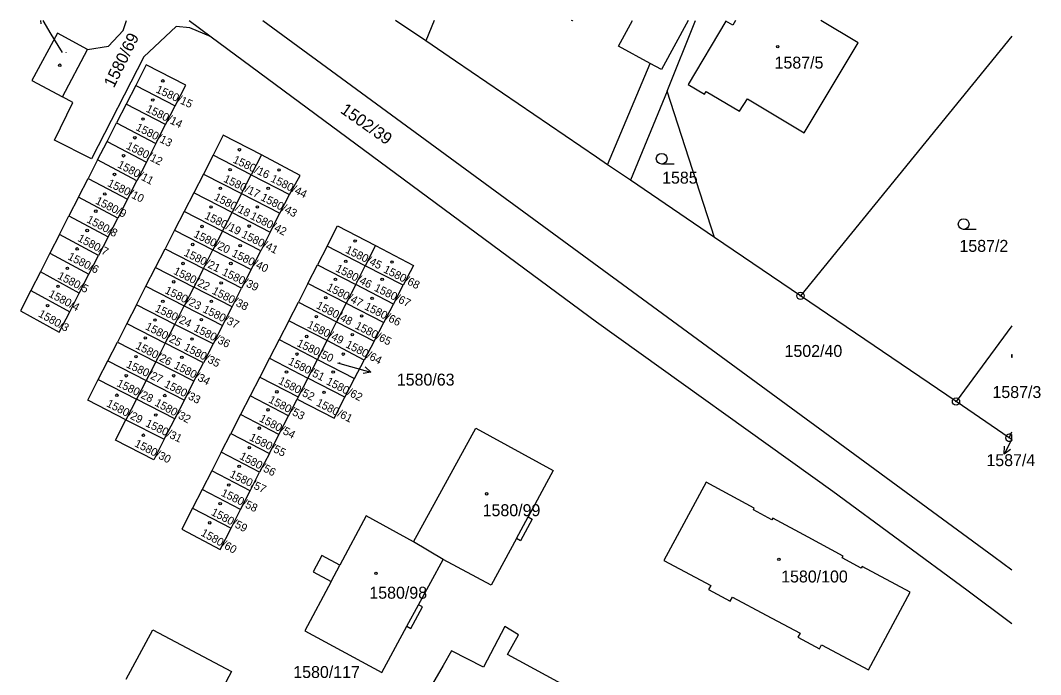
# Model space of a CAD drawing. Extents: x -736397 to -735924, y -1118983 to -1118245.
# Drawn here: x -736069.2 to -735924, y -1118338 to -1118244.9 of the extents above; entities that cross this region are included whole.
import ezdxf

# ---------------------------------------------------------------- set-up
doc = ezdxf.new("R2010")
doc.units = 0
for name, color, linetype in [('Vrstva 1', 7, 'Continuous'), ('Vrstva 16', 7, 'Continuous'), ('Vrstva 18', 7, 'Continuous'), ('Vrstva 19', 7, 'Continuous'), ('Vrstva 25', 7, 'Continuous'), ('Vrstva 4', 7, 'Continuous')]:
    doc.layers.add(name, color=color, linetype=linetype)

msp = doc.modelspace()

# ---------------------------------------------------------------- linework, layer by layer
at = {"layer": 'Vrstva 1'}
for p, q in [((-736045.18, -1118244.9), (-736042.03, -1118247.22)), ((-736011.5, -1118247.82), (-736015.8, -1118244.9)), ((-736010.3, -1118244.9), (-736011.5, -1118247.82)), ((-735928.04, -1118247.13), (-735958.15, -1118284.08)), ((-736063.22, -1118255.78), (-736059.67, -1118249.01)), ((-735985.62, -1118265.43), (-735979.55, -1118251.02)), ((-736052.8, -1118254.16), (-736054.14, -1118256.79)), ((-736052.8, -1118254.16), (-736047.17, -1118257.06)), ((-735977.15, -1118254.97), (-735982.36, -1118267.64)), ((-735970.38, -1118275.78), (-735977.15, -1118254.97)), ((-736054.14, -1118256.79), (-736055.53, -1118259.48)), ((-736048.53, -1118259.7), (-736054.14, -1118256.79)), ((-736048.53, -1118259.7), (-736047.17, -1118257.06)), ((-736056.88, -1118262.13), (-736055.53, -1118259.48)), ((-736055.53, -1118259.48), (-736049.91, -1118262.41)), ((-736049.91, -1118262.41), (-736048.53, -1118259.7)), ((-736058.23, -1118264.75), (-736056.88, -1118262.13)), ((-736056.88, -1118262.13), (-736051.28, -1118265.07)), ((-736049.91, -1118262.41), (-736051.28, -1118265.07)), ((-736058.23, -1118264.75), (-736059.57, -1118267.39)), ((-736052.63, -1118267.71), (-736058.23, -1118264.75)), ((-736041.79, -1118264.08), (-736043.16, -1118266.75)), ((-736036.34, -1118266.87), (-736041.79, -1118264.08)), ((-736034.89, -1118264.03), (-736036.34, -1118266.87)), ((-736051.28, -1118265.07), (-736052.63, -1118267.71)), ((-735982.36, -1118267.64), (-735985.62, -1118265.43)), ((-736060.94, -1118270.06), (-736059.57, -1118267.39)), ((-736059.57, -1118267.39), (-736053.98, -1118270.35)), ((-736053.98, -1118270.35), (-736052.63, -1118267.71)), ((-736043.16, -1118266.75), (-736044.52, -1118269.42)), ((-736043.16, -1118266.75), (-736037.71, -1118269.54)), ((-736037.71, -1118269.54), (-736036.34, -1118266.87)), ((-736036.34, -1118266.87), (-736030.89, -1118269.66)), ((-735970.38, -1118275.78), (-735982.36, -1118267.64)), ((-736060.94, -1118270.06), (-736062.3, -1118272.71)), ((-736055.36, -1118273.04), (-736060.94, -1118270.06)), ((-736053.98, -1118270.35), (-736055.36, -1118273.04)), ((-736044.52, -1118269.42), (-736045.89, -1118272.08)), ((-736039.08, -1118272.21), (-736044.52, -1118269.42)), ((-736037.71, -1118269.54), (-736039.08, -1118272.21)), ((-736037.71, -1118269.54), (-736032.26, -1118272.33)), ((-736032.26, -1118272.33), (-736030.89, -1118269.66)), ((-736045.89, -1118272.08), (-736047.25, -1118274.74)), ((-736040.44, -1118274.87), (-736045.89, -1118272.08)), ((-736040.44, -1118274.87), (-736039.08, -1118272.21)), ((-736039.08, -1118272.21), (-736033.63, -1118275)), ((-736063.65, -1118275.35), (-736062.3, -1118272.71)), ((-736062.3, -1118272.71), (-736056.73, -1118275.7)), ((-736056.73, -1118275.7), (-736055.36, -1118273.04)), ((-736033.63, -1118275), (-736032.26, -1118272.33)), ((-736047.25, -1118274.74), (-736048.61, -1118277.4)), ((-736047.25, -1118274.74), (-736041.8, -1118277.52)), ((-736040.44, -1118274.87), (-736041.8, -1118277.52)), ((-736034.99, -1118277.66), (-736040.44, -1118274.87)), ((-736033.63, -1118275), (-736034.99, -1118277.66)), ((-736063.65, -1118275.35), (-736065.01, -1118278)), ((-736058.09, -1118278.36), (-736063.65, -1118275.35)), ((-736056.73, -1118275.7), (-736058.09, -1118278.36)), ((-735958.15, -1118284.08), (-735970.38, -1118275.78)), ((-736065.01, -1118278), (-736066.37, -1118280.67)), ((-736065.01, -1118278), (-736059.45, -1118281.02)), ((-736049.97, -1118280.06), (-736048.61, -1118277.4)), ((-736048.61, -1118277.4), (-736043.16, -1118280.19)), ((-736043.16, -1118280.19), (-736041.8, -1118277.52)), ((-736041.8, -1118277.52), (-736036.35, -1118280.31)), ((-736036.35, -1118280.31), (-736034.99, -1118277.66)), ((-736025.55, -1118277), (-736026.91, -1118279.65)), ((-736020.11, -1118279.8), (-736025.55, -1118277)), ((-736018.64, -1118276.93), (-736020.11, -1118279.8)), ((-736059.45, -1118281.02), (-736058.09, -1118278.36)), ((-736066.37, -1118280.67), (-736067.73, -1118283.31)), ((-736060.83, -1118283.7), (-736066.37, -1118280.67)), ((-736051.33, -1118282.71), (-736049.97, -1118280.06)), ((-736049.97, -1118280.06), (-736044.53, -1118282.85)), ((-736043.16, -1118280.19), (-736044.53, -1118282.85)), ((-736037.71, -1118282.97), (-736043.16, -1118280.19)), ((-736036.35, -1118280.31), (-736037.71, -1118282.97)), ((-736028.27, -1118282.31), (-736026.91, -1118279.65)), ((-736026.91, -1118279.65), (-736021.46, -1118282.45)), ((-736021.46, -1118282.45), (-736020.11, -1118279.8)), ((-736014.71, -1118282.58), (-736020.11, -1118279.8)), ((-736060.83, -1118283.7), (-736059.45, -1118281.02)), ((-736028.27, -1118282.31), (-736029.64, -1118284.98)), ((-736022.83, -1118285.11), (-736028.27, -1118282.31)), ((-736067.73, -1118283.31), (-736062.19, -1118286.35)), ((-736062.19, -1118286.35), (-736060.83, -1118283.7)), ((-736052.68, -1118285.35), (-736051.33, -1118282.71)), ((-736051.33, -1118282.71), (-736045.88, -1118285.5)), ((-736044.53, -1118282.85), (-736045.88, -1118285.5)), ((-736039.08, -1118285.64), (-736044.53, -1118282.85)), ((-736039.08, -1118285.64), (-736037.71, -1118282.97)), ((-736021.46, -1118282.45), (-736022.83, -1118285.11)), ((-736016.09, -1118285.25), (-736021.46, -1118282.45)), ((-736016.09, -1118285.25), (-736014.71, -1118282.58)), ((-736031.01, -1118287.64), (-736029.64, -1118284.98)), ((-736029.64, -1118284.98), (-736024.2, -1118287.79)), ((-736022.83, -1118285.11), (-736024.2, -1118287.79)), ((-736022.83, -1118285.11), (-736017.48, -1118287.89)), ((-736017.48, -1118287.89), (-736016.09, -1118285.25)), ((-735936.01, -1118299.12), (-735958.15, -1118284.08)), ((-736052.68, -1118285.35), (-736054.05, -1118288.02)), ((-736047.24, -1118288.14), (-736052.68, -1118285.35)), ((-736047.24, -1118288.14), (-736045.88, -1118285.5)), ((-736045.88, -1118285.5), (-736040.44, -1118288.29)), ((-736040.44, -1118288.29), (-736039.08, -1118285.64)), ((-736054.05, -1118288.02), (-736055.4, -1118290.66)), ((-736054.05, -1118288.02), (-736048.6, -1118290.81)), ((-736048.6, -1118290.81), (-736047.24, -1118288.14)), ((-736041.79, -1118290.93), (-736047.24, -1118288.14)), ((-736031.01, -1118287.64), (-736032.38, -1118290.31)), ((-736025.56, -1118290.45), (-736031.01, -1118287.64)), ((-736025.56, -1118290.45), (-736024.2, -1118287.79)), ((-736024.2, -1118287.79), (-736018.86, -1118290.55)), ((-736018.86, -1118290.55), (-736017.48, -1118287.89)), ((-736040.44, -1118288.29), (-736041.79, -1118290.93)), ((-735928.04, -1118288.37), (-735936.01, -1118299.12)), ((-736056.76, -1118293.32), (-736055.4, -1118290.66)), ((-736055.4, -1118290.66), (-736049.95, -1118293.45)), ((-736048.6, -1118290.81), (-736049.95, -1118293.45)), ((-736043.15, -1118293.59), (-736048.6, -1118290.81)), ((-736041.79, -1118290.93), (-736043.15, -1118293.59)), ((-736032.38, -1118290.31), (-736033.75, -1118292.97)), ((-736032.38, -1118290.31), (-736026.93, -1118293.13)), ((-736026.93, -1118293.13), (-736025.56, -1118290.45)), ((-736020.25, -1118293.22), (-736025.56, -1118290.45)), ((-736018.86, -1118290.55), (-736020.25, -1118293.22)), ((-736058.12, -1118295.98), (-736056.76, -1118293.32)), ((-736056.76, -1118293.32), (-736051.32, -1118296.11)), ((-736049.95, -1118293.45), (-736051.32, -1118296.11)), ((-736044.51, -1118296.24), (-736049.95, -1118293.45)), ((-736044.51, -1118296.24), (-736043.15, -1118293.59)), ((-736033.75, -1118292.97), (-736035.12, -1118295.63)), ((-736033.75, -1118292.97), (-736028.3, -1118295.79)), ((-736028.3, -1118295.79), (-736026.93, -1118293.13)), ((-736026.93, -1118293.13), (-736021.63, -1118295.86)), ((-736021.63, -1118295.86), (-736020.25, -1118293.22)), ((-736058.12, -1118295.98), (-736052.68, -1118298.77)), ((-736051.32, -1118296.11), (-736052.68, -1118298.77)), ((-736051.32, -1118296.11), (-736045.87, -1118298.9)), ((-736045.87, -1118298.9), (-736044.51, -1118296.24)), ((-736035.12, -1118295.63), (-736036.49, -1118298.31)), ((-736035.12, -1118295.63), (-736029.66, -1118298.46)), ((-736028.3, -1118295.79), (-736029.66, -1118298.46)), ((-736023.01, -1118298.51), (-736028.3, -1118295.79)), ((-736023.01, -1118298.51), (-736021.63, -1118295.86)), ((-736036.49, -1118298.31), (-736037.86, -1118300.97)), ((-736031.03, -1118301.14), (-736036.49, -1118298.31)), ((-736052.68, -1118298.77), (-736054.18, -1118301.7)), ((-736047.23, -1118301.56), (-736052.68, -1118298.77)), ((-736047.23, -1118301.56), (-736045.87, -1118298.9)), ((-736031.03, -1118301.14), (-736029.83, -1118298.78)), ((-736029.66, -1118298.46), (-736029.83, -1118298.78)), ((-735928.43, -1118304.27), (-735936.01, -1118299.12)), ((-736037.86, -1118300.97), (-736039.23, -1118303.65)), ((-736032.4, -1118303.8), (-736037.86, -1118300.97)), ((-736032.4, -1118303.8), (-736031.03, -1118301.14)), ((-736054.18, -1118301.7), (-736048.73, -1118304.49)), ((-736048.73, -1118304.49), (-736047.23, -1118301.56)), ((-736040.62, -1118306.34), (-736039.23, -1118303.65)), ((-736039.23, -1118303.65), (-736033.77, -1118306.49)), ((-736033.77, -1118306.49), (-736032.4, -1118303.8)), ((-735928.43, -1118304.27), (-735928.04, -1118303.42)), ((-735928.04, -1118304.54), (-735928.43, -1118304.27)), ((-736040.62, -1118306.34), (-736041.97, -1118308.98)), ((-736035.15, -1118309.18), (-736040.62, -1118306.34)), ((-736033.77, -1118306.49), (-736035.15, -1118309.18)), ((-736041.97, -1118308.98), (-736043.33, -1118311.62)), ((-736036.51, -1118311.83), (-736041.97, -1118308.98)), ((-736036.51, -1118311.83), (-736035.15, -1118309.18)), ((-736043.33, -1118311.62), (-736044.69, -1118314.28)), ((-736037.86, -1118314.47), (-736043.33, -1118311.62)), ((-736037.86, -1118314.47), (-736036.51, -1118311.83)), ((-736044.69, -1118314.28), (-736039.22, -1118317.13)), ((-736039.22, -1118317.13), (-736037.86, -1118314.47)), ((-736009.04, -1118321.61), (-736013.25, -1118319.07)), ((-736012.51, -1118328.04), (-736009.04, -1118321.61))]:
    msp.add_line(p, q, dxfattribs=at)
for points in [[(-736042.03, -1118247.22), (-736045.09, -1118245.93), (-736047.04, -1118245.74), (-736051.64, -1118250.06), (-736059.1, -1118264.58), (-736064.37, -1118261.94), (-736061.75, -1118256.56), (-736063.22, -1118255.78)], [(-736059.67, -1118249.01), (-736056.67, -1118248.57), (-736054.58, -1118246.33), (-736054.12, -1118244.9)], [(-736034.7, -1118244.9), (-735949.71, -1118307.16), (-735930.63, -1118321.15), (-735928.04, -1118323.05)], [(-735990.57, -1118244.9), (-735990.61, -1118244.96), (-735990.73, -1118244.9)], [(-735979.55, -1118251.02), (-735984.08, -1118248.56), (-735982.09, -1118244.9)], [(-735974.12, -1118244.9), (-735977.96, -1118251.89), (-735979.55, -1118251.02)], [(-735977.15, -1118254.97), (-735973.12, -1118244.9)], [(-735967.78, -1118245.57), (-735968.76, -1118244.98), (-735974.14, -1118254), (-735971.8, -1118255.4), (-735971.57, -1118255.02), (-735966.81, -1118257.83), (-735965.71, -1118256.03), (-735957.63, -1118260.87), (-735949.95, -1118248.07), (-735955.25, -1118244.9)], [(-735967.38, -1118244.9), (-735967.78, -1118245.57)], [(-736059.67, -1118249.01), (-736063.94, -1118246.71), (-736067.56, -1118253.45), (-736063.22, -1118255.78)], [(-736042.03, -1118247.22), (-735987.19, -1118287.78), (-735953.53, -1118311.86), (-735934.46, -1118325.93), (-735928.04, -1118330.7)], [(-735985.62, -1118265.43), (-735987.2, -1118264.36), (-735993.86, -1118259.82), (-736007.28, -1118250.69), (-736011.5, -1118247.82)], [(-736047.17, -1118257.06), (-736045.66, -1118254.11), (-736051.3, -1118251.22), (-736052.8, -1118254.16)], [(-736034.89, -1118264.03), (-736040.33, -1118261.24), (-736041.79, -1118264.08)], [(-736030.89, -1118269.66), (-736029.38, -1118266.95), (-736034.89, -1118264.03)], [(-736025.55, -1118277), (-736024.08, -1118274.14), (-736018.64, -1118276.93)], [(-736018.64, -1118276.93), (-736013.25, -1118279.78), (-736014.71, -1118282.58)], [(-736067.73, -1118283.31), (-736069.21, -1118286.21), (-736063.68, -1118289.26), (-736062.19, -1118286.35)], [(-736054.18, -1118301.7), (-736059.62, -1118298.91), (-736058.12, -1118295.98)], [(-736029.83, -1118298.78), (-736024.56, -1118301.48), (-736023.01, -1118298.51)], [(-736048.73, -1118304.49), (-736050.22, -1118307.4), (-736055.67, -1118304.61), (-736054.18, -1118301.7)], [(-736013.25, -1118319.07), (-736004.39, -1118302.89), (-735993.36, -1118308.95), (-735996.93, -1118315.54)], [(-735963.03, -1118329.52), (-735958.22, -1118332.09), (-735958.53, -1118332.66), (-735955.44, -1118334.31), (-735955.14, -1118333.74), (-735948.48, -1118337.3), (-735942.52, -1118326.26), (-735949.37, -1118322.57), (-735949.51, -1118322.82), (-735952.2, -1118321.36), (-735952.07, -1118321.11), (-735957.07, -1118318.42), (-735962.08, -1118315.73), (-735962.21, -1118315.97), (-735964.86, -1118314.54), (-735964.73, -1118314.3), (-735971.6, -1118310.59), (-735977.6, -1118321.72), (-735970.93, -1118325.29), (-735971.25, -1118325.88), (-735968.16, -1118327.53), (-735967.84, -1118326.94), (-735963.03, -1118329.52)], [(-736044.69, -1118314.28), (-736046.24, -1118317.3), (-736040.77, -1118320.15), (-736039.22, -1118317.13)], [(-736013.25, -1118319.07), (-736019.99, -1118315.38), (-736023.73, -1118322.39)], [(-735996.93, -1118315.54), (-735996.36, -1118315.85), (-735998.03, -1118318.93), (-735998.6, -1118318.62)], [(-735998.6, -1118318.62), (-736002.18, -1118325.23), (-736009.04, -1118321.61)], [(-736023.73, -1118322.39), (-736026.29, -1118321.02), (-736027.54, -1118323.36), (-736024.98, -1118324.72)], [(-736024.98, -1118324.72), (-736028.73, -1118331.75), (-736017.77, -1118337.69), (-736014.2, -1118331.09)], [(-736014.2, -1118331.09), (-736013.61, -1118331.41), (-736011.95, -1118328.34), (-736012.51, -1118328.04)], [(-736054.14, -1118338.61), (-736050.34, -1118331.61), (-736039.16, -1118337.53), (-736042.72, -1118344.22)], [(-735998.8, -1118364.6), (-735994.62, -1118357.18), (-735993.05, -1118358.05), (-735985, -1118343.15), (-735999.87, -1118335.12), (-735998.28, -1118332.29), (-736000.23, -1118331.14), (-736003.3, -1118336.9), (-736007.84, -1118334.58), (-736009.02, -1118336.69), (-736012.85, -1118343.25)]]:
    msp.add_lwpolyline(points, dxfattribs=at)
at = {"layer": 'Vrstva 16'}
for points in [[(-736066.27, -1118245.39), (-736066.31, -1118244.9)], [(-736063.21, -1118249.48), (-736064.81, -1118246.84), (-736065.99, -1118244.9)], [(-736024.07, -1118293.59), (-736022.21, -1118294.12), (-736019.33, -1118294.94)], [(-736020.15, -1118294.19), (-736019.33, -1118294.94), (-736020.42, -1118295.15)], [(-735928.04, -1118304.46), (-735929.13, -1118306.6)], [(-735928.23, -1118305.94), (-735929.13, -1118306.6), (-735929.12, -1118305.49)]]:
    msp.add_lwpolyline(points, dxfattribs=at)
at = {"layer": 'Vrstva 25'}
for p, q in [((-735976.13, -1118265.33), (-735977.91, -1118265.33)), ((-735933.14, -1118274.63), (-735934.92, -1118274.63)), ((-735928.04, -1118292.87), (-735928.04, -1118292.41)), ((-735928.04, -1118304.6), (-735928.04, -1118303.94))]:
    msp.add_line(p, q, dxfattribs=at)
for centre, major_axis, ratio in [((-735961.39, -1118248.62), (0.18, 0), 0.984808), ((-736063.61, -1118251.27), (0.18, 0), 0.984808), ((-736048.93, -1118253.5), (0.18, 0), 0.984808), ((-736050.37, -1118256.22), (0.18, 0), 0.984808), ((-736051.75, -1118258.93), (0.18, 0), 0.984808), ((-736052.92, -1118261.59), (0.18, 0), 0.984808), ((-736038.03, -1118263.3), (0.18, 0), 0.984808), ((-736054.52, -1118264.15), (0.18, 0), 0.984808), ((-735977.91, -1118264.57), (0.764, 0), 0.989424), ((-736039.36, -1118266.12), (0.18, 0), 0.984808), ((-736032.39, -1118266.17), (0.18, 0), 0.984808), ((-736055.82, -1118266.81), (0.18, 0), 0.984808), ((-736040.74, -1118268.78), (0.18, 0), 0.984808), ((-736033.93, -1118268.78), (0.18, 0), 0.984808), ((-736057.2, -1118269.58), (0.18, 0), 0.984808), ((-736058.48, -1118272.03), (0.18, 0), 0.984808), ((-736042.07, -1118271.44), (0.18, 0), 0.984808), ((-736035.47, -1118271.44), (0.18, 0), 0.984808), ((-735934.92, -1118273.87), (0.764, 0), 0.989424), ((-736059.7, -1118274.79), (0.18, 0), 0.984808), ((-736043.35, -1118274.21), (0.18, 0), 0.984808), ((-736036.64, -1118274.16), (0.18, 0), 0.984808), ((-736044.68, -1118276.77), (0.18, 0), 0.984808), ((-736021.56, -1118276.29), (0.18, 0), 0.984808), ((-736061.14, -1118277.4), (0.18, 0), 0.984808), ((-736037.92, -1118276.93), (0.18, 0), 0.984808), ((-736046.06, -1118279.48), (0.18, 0), 0.984808), ((-736039.25, -1118279.48), (0.18, 0), 0.984808), ((-736022.89, -1118279.16), (0.18, 0), 0.984808), ((-736016.3, -1118279.27), (0.18, 0), 0.984808), ((-736062.52, -1118280.17), (0.18, 0), 0.984808), ((-736047.39, -1118282.09), (0.18, 0), 0.984808), ((-736040.63, -1118282.25), (0.18, 0), 0.984808), ((-736024.36, -1118281.72), (0.18, 0), 0.984808), ((-736017.71, -1118281.72), (0.18, 0), 0.984808), ((-736063.85, -1118282.73), (0.18, 0), 0.984808), ((-735958.15, -1118284.08), (0.516, 0), 0.984808), ((-736048.93, -1118284.86), (0.18, 0), 0.984808), ((-736042.02, -1118284.86), (0.18, 0), 0.984808), ((-736025.74, -1118284.33), (0.18, 0), 0.984808), ((-736019.14, -1118284.43), (0.18, 0), 0.984808), ((-735958.15, -1118284.08), (0.0375, 0), 0.984808), ((-736065.34, -1118285.49), (0.18, 0), 0.984808), ((-736050.05, -1118287.52), (0.18, 0), 0.984808), ((-736043.45, -1118287.46), (0.18, 0), 0.984808), ((-736027.07, -1118287.04), (0.18, 0), 0.984808), ((-736020.63, -1118286.94), (0.18, 0), 0.984808), ((-736021.96, -1118289.6), (0.18, 0), 0.984808), ((-736051.43, -1118290.07), (0.18, 0), 0.984808), ((-736044.78, -1118290.23), (0.18, 0), 0.984808), ((-736028.45, -1118289.86), (0.18, 0), 0.984808), ((-736052.76, -1118292.73), (0.18, 0), 0.984808), ((-736029.84, -1118292.37), (0.18, 0), 0.984808), ((-736023.24, -1118292.37), (0.18, 0), 0.984808), ((-736046.22, -1118292.84), (0.18, 0), 0.984808), ((-736054.14, -1118295.45), (0.18, 0), 0.984808), ((-736047.39, -1118295.45), (0.18, 0), 0.984808), ((-736031.33, -1118294.92), (0.18, 0), 0.984808), ((-736024.68, -1118294.92), (0.18, 0), 0.984808), ((-736055.47, -1118298.22), (0.18, 0), 0.984808), ((-736048.66, -1118298.27), (0.18, 0), 0.984808), ((-736032.69, -1118297.74), (0.18, 0), 0.984808), ((-736025.98, -1118297.8), (0.18, 0), 0.984808), ((-735936.01, -1118299.12), (0.516, 0), 0.984808), ((-735936.01, -1118299.12), (0.0375, 0), 0.984808), ((-736049.94, -1118301.04), (0.18, 0), 0.984808), ((-736033.96, -1118300.3), (0.18, 0), 0.984808), ((-736035.19, -1118302.91), (0.18, 0), 0.984808), ((-736051.7, -1118303.91), (0.18, 0), 0.984808), ((-736036.62, -1118305.67), (0.18, 0), 0.984808), ((-735928.43, -1118304.27), (0.0375, 0), 0.984808), ((-736038.06, -1118308.34), (0.18, 0), 0.984808), ((-736039.55, -1118311), (0.18, 0), 0.984808), ((-736002.83, -1118312.25), (0.18, 0), 0.984808), ((-736040.77, -1118313.66), (0.18, 0), 0.984808), ((-736042.26, -1118316.37), (0.18, 0), 0.984808), ((-735961.22, -1118321.56), (0.18, 0), 0.984808), ((-736018.59, -1118323.56), (0.18, 0), 0.984808)]:
    msp.add_ellipse(centre, major_axis=major_axis, ratio=ratio, dxfattribs=at)
for centre, major_axis, ratio, start_param, end_param in [((-735927.31, -1118292.64), (0.764, 0), 0.989424, 2.831664, 3.451522), ((-735928.43, -1118304.27), (0.516, 0), 0.984808, 0.705218, 5.577968)]:
    msp.add_ellipse(centre, major_axis=major_axis, ratio=ratio, start_param=start_param, end_param=end_param, dxfattribs=at)
at = {"layer": 'Vrstva 4'}
for p, q in [((-735998.6, -1118318.62), (-735996.93, -1118315.54)), ((-736024.98, -1118324.72), (-736023.73, -1118322.39)), ((-736014.2, -1118331.09), (-736012.51, -1118328.04))]:
    msp.add_line(p, q, dxfattribs=at)

# ---------------------------------------------------------------- texts
at = {"layer": 'Vrstva 16'}
for s, p in [('1580/63', (-736015.62, -1118296.85)), ('1587/4', (-735931.68, -1118308.31)), ('1580/117', (-736030.36, -1118338.45))]:
    msp.add_text(s, height=1.7, dxfattribs=at).set_placement(p)
at = {"layer": 'Vrstva 18'}
for s, rotation, p in [('1580/69', 63.7441, (-736055.9, -1118254.59)), ('1502/39', 324.7645, (-736023.78, -1118257.94))]:
    msp.add_text(s, height=1.7, rotation=rotation, dxfattribs=at).set_placement(p)
for s, p in [('1585', (-735977.85, -1118268.12)), ('1587/2', (-735935.52, -1118277.82)), ('1502/40', (-735960.42, -1118292.77)), ('1587/3', (-735930.82, -1118298.62))]:
    msp.add_text(s, height=1.7, dxfattribs=at).set_placement(p)
at = {"layer": 'Vrstva 19'}
for s, height, p in [('1580/89', 0.1, (-736063.01, -1118249.48)), ('1587/5', 1.7, (-735961.84, -1118251.75)), ('1580/63', 0.1, (-736024.07, -1118293.59)), ('1580/99', 1.7, (-736003.4, -1118315.43)), ('1580/100', 1.7, (-735960.9, -1118324.86)), ('1580/98', 1.7, (-736019.53, -1118327.17))]:
    msp.add_text(s, height=height, dxfattribs=at).set_placement(p)
for s, rotation, p in [('1580/15', 335.3197, (-736050.02, -1118255.1)), ('1580/14', 333.693, (-736051.43, -1118257.82)), ('1580/13', 333.2219, (-736052.88, -1118260.45)), ('1580/12', 333.4058, (-736054.25, -1118263.1)), ('1580/11', 332.295, (-736055.49, -1118265.75)), ('1580/16', 334.6186, (-736039.05, -1118265.08)), ('1580/10', 333.7833, (-736056.91, -1118268.41)), ('1580/17', 334.3413, (-736040.39, -1118267.81)), ('1580/44', 333.6259, (-736033.69, -1118267.77)), ('1580/9', 333.1722, (-736058.63, -1118270.91)), ('1580/18', 332.6041, (-736041.75, -1118270.37)), ('1580/43', 332.6811, (-736035.09, -1118270.42)), ('1580/19', 333.7671, (-736043.1, -1118273.04)), ('1580/42', 333.066, (-736036.58, -1118273.06)), ('1580/8', 331.8045, (-736059.88, -1118273.56)), ('1580/20', 333.5573, (-736044.65, -1118275.66)), ('1580/41', 333.8009, (-736037.83, -1118275.71)), ('1580/7', 331.9105, (-736061.16, -1118276.22)), ('1580/6', 333.066, (-736062.57, -1118278.84)), ('1580/21', 333.5945, (-736046.04, -1118278.31)), ('1580/40', 334.2039, (-736039.22, -1118278.4)), ('1580/45', 333.6228, (-736023.04, -1118277.89)), ('1580/5', 332.6459, (-736064.02, -1118281.58)), ('1580/22', 333.6819, (-736047.52, -1118280.92)), ('1580/39', 334.2055, (-736040.6, -1118281.06)), ('1580/46', 332.7447, (-736024.44, -1118280.53)), ('1580/68', 333.1485, (-736017.63, -1118280.68)), ('1580/47', 332.8008, (-736025.71, -1118283.19)), ('1580/4', 332.1796, (-736065.3, -1118284.14)), ('1580/23', 333.4863, (-736048.75, -1118283.65)), ('1580/38', 332.9986, (-736042.03, -1118283.72)), ('1580/67', 333.9509, (-736018.94, -1118283.31)), ('1580/48', 332.8168, (-736027.2, -1118285.8)), ('1580/66', 333.2594, (-736020.33, -1118285.95)), ('1580/3', 330.7512, (-736066.76, -1118286.96)), ('1580/24', 334.392, (-736050.16, -1118286.23)), ('1580/37', 333.6808, (-736043.35, -1118286.35)), ('1580/25', 332.6114, (-736051.53, -1118288.79)), ('1580/36', 333.1046, (-736044.63, -1118289.03)), ('1580/49', 333.3978, (-736028.47, -1118288.54)), ('1580/65', 332.8876, (-736021.67, -1118288.67)), ('1580/26', 332.3757, (-736052.91, -1118291.51)), ('1580/35', 332.2658, (-736046.03, -1118291.73)), ('1580/50', 334.309, (-736029.95, -1118291.18)), ('1580/64', 332.6532, (-736023.01, -1118291.34)), ('1580/27', 334.6579, (-736054.25, -1118294.2)), ('1580/34', 332.5531, (-736047.46, -1118294.32)), ('1580/51', 333.4001, (-736031.18, -1118293.76)), ('1580/28', 333.9046, (-736055.59, -1118296.88)), ('1580/33', 332.8986, (-736048.83, -1118296.98)), ('1580/52', 332.6553, (-736032.59, -1118296.51)), ('1580/62', 332.7795, (-736025.77, -1118296.6)), ('1580/53', 331.9969, (-736033.98, -1118299.19)), ('1580/29', 332.5997, (-736057.06, -1118299.75)), ('1580/32', 331.4538, (-736050.19, -1118299.63)), ('1580/61', 332.9111, (-736027.2, -1118299.64)), ('1580/54', 331.805, (-736035.31, -1118301.86)), ('1580/31', 334.0238, (-736051.5, -1118302.58)), ('1580/55', 333.59, (-736036.71, -1118304.56)), ('1580/30', 332.9111, (-736053.06, -1118305.44)), ('1580/56', 332.1067, (-736038.11, -1118307.22)), ('1580/57', 334.1682, (-736039.52, -1118309.81)), ('1580/58', 334.0703, (-736040.74, -1118312.48)), ('1580/59', 332.418, (-736042.16, -1118315.2)), ('1580/60', 330.852, (-736043.62, -1118318.12))]:
    msp.add_text(s, height=1.14, rotation=rotation, dxfattribs=at).set_placement(p)

doc.saveas('drawing.dxf')
